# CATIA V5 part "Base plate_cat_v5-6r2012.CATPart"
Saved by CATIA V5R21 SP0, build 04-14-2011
Part number: Base Plate
Bounding box of the stored display mesh (mm): x -10 to 10, y 0 to 144, z 0 to 6
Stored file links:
  D:\CATIA V5R21 E-RESOURCES\CATIA-V5R21\catia-v5r21-prt\c16-catia-v5r20-prt\c16-catia-v5r21-tut01\CAT_V5R21_Base.CATPart
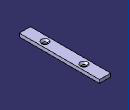
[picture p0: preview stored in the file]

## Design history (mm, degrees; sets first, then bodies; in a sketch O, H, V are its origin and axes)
Body1 (main body)
  Sketch1 on zx-plane, origin (0, 0, 0), H (-1, 0, 0), V (0, 0, 1)
    point P1 (-10, 0)
    line L1 (-10, 0) -> (10, 0)
    line L2 (10, 0) -> (10, 6)
    line L3 (10, 6) -> (-10, 6)
    line L4 (-10, 6) -> (-10, 0)
    length L3 = 20
    length L2 = 6
    distance V L2 = 10
    coincidence: P1 H
    horizontal: L1 H, L3 H
    vertical: L2 V, L4 V
  Pad1: profile Sketch1, direction (0, 1, 0), length 144
  Sketch2 on face of Pad1, origin (-6.0071, 115.251, 6), H (1, 0, 0), V (0, 1, 0)
    point P1 (6.0071, -9.251)
    reference projected line E1 (-3.9929, -115.251) -> (-3.9929, 28.749) from edge of Pad1
    reference projected line E2 (16.0071, 28.749) -> (-3.9929, 28.749) from edge of Pad1
    distance E1 P1 = 10
    distance E2 P1 = 38
  Hole1: placed by Sketch2, at (0, 106, 6) direction (0, 0, -1), diameter 7, through (limit type 6), countersink depth 3, countersink angle 90
  RectPattern1: of Hole1, direction 1 instances 2, spacing 70, along edge of Pad1 reversed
